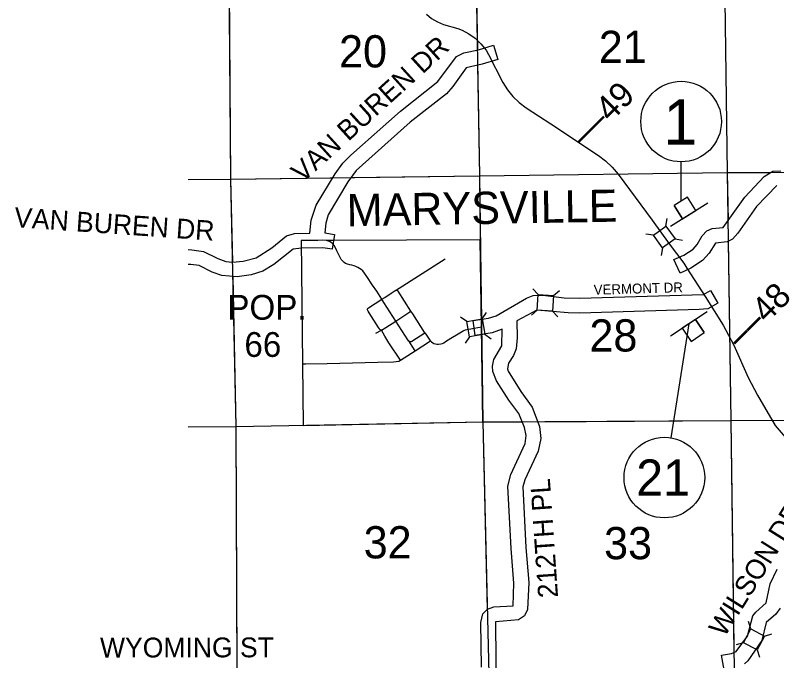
# Model space of a CAD drawing. Extents: x 10133 to 81668, y 5524 to 11018.
# Drawn here: x 22990.7 to 23374.6, y 8304.5 to 8630.1 of the extents above; entities that cross this region are included whole.
import ezdxf

# ---------------------------------------------------------------- set-up
doc = ezdxf.new("R2010")
doc.units = 0
for name, color, linetype in [('Default', 7, 'Continuous'), ('DisBoundDim', 7, 'Continuous'), ('DisCLMLOR', 7, 'Continuous'), ('DisCLMLSUR', 7, 'Continuous'), ('trf_SignNumber_Text', 7, 'Continuous')]:
    doc.layers.add(name, color=color, linetype=linetype)

msp = doc.modelspace()

# ---------------------------------------------------------------- linework, layer by layer
at = {"layer": 'Default'}
for p, q in [((23318.72, 8523.69), (23319.35, 8527.55)), ((23312.36, 8519.13), (23308.5, 8519.76)), ((23323.28, 8517.33), (23327.14, 8516.7)), ((23316.93, 8512.77), (23316.29, 8508.91)), ((23254.27, 8489.24), (23251.67, 8492.17)), ((23262.08, 8488.76), (23265.01, 8491.35)), ((23253.79, 8481.43), (23250.86, 8478.83)), ((23261.6, 8480.95), (23264.19, 8478.02)), ((23218.34, 8475.62), (23215.15, 8477.88)), ((23226.05, 8476.96), (23228.31, 8480.16)), ((23227.39, 8469.25), (23230.59, 8467)), ((23219.68, 8467.91), (23217.43, 8464.72)), ((23361.49, 8320.59), (23360.33, 8324.32)), ((23368.42, 8316.94), (23372.16, 8318.1)), ((23357.85, 8313.66), (23354.11, 8312.5)), ((23364.77, 8310.02), (23365.93, 8306.28))]:
    msp.add_line(p, q, dxfattribs=at)
for points in [[(23098.21, 8672.61), (23099.25, 8547.47)], [(23222.61, 8674.33), (23223.65, 8612.58)], [(23222.61, 8674.33), (23224.71, 8549.21)], [(23347.95, 8674.98), (23349.65, 8550.78)], [(23347.95, 8674.98), (23349.65, 8550.78)], [(23098.45, 8643.94), (23099.25, 8547.47)], [(23197.97, 8630.68), (23200.59, 8628.51), (23203.51, 8626.75), (23206.66, 8625.44), (23213.77, 8623.53), (23216.07, 8622.59), (23219.42, 8620.81), (23222.51, 8618.6), (23225.42, 8615.72), (23228.03, 8612.56), (23229.23, 8610.29), (23236.44, 8596.25), (23238.76, 8592.52), (23241.52, 8589.1), (23244.68, 8586.04), (23248.18, 8583.38), (23260.61, 8575.38), (23284.71, 8559.38), (23288.31, 8556.64), (23291.57, 8553.51), (23294.55, 8549.94), (23311.75, 8526.77), (23320.26, 8514.81), (23327.73, 8505.03), (23329.17, 8502.59), (23338.51, 8488.26), (23347.55, 8473.86), (23352.91, 8463.81), (23360.18, 8447.48), (23364.81, 8438.57), (23373.81, 8423.25), (23378.83, 8417.33)], [(23077.9, 8511.95), (23079.75, 8511.85), (23085.66, 8511.02), (23092.78, 8507.43), (23096.91, 8506.01), (23100.2, 8505.63), (23105.64, 8506.07), (23112.18, 8507.86), (23120.04, 8512.89), (23127.43, 8518.93), (23131.39, 8519.98), (23139.24, 8520.21), (23139.94, 8526.73), (23142.36, 8534.42), (23151.95, 8550.14), (23155.87, 8555.57), (23159.79, 8559.64), (23184.9, 8581.79), (23203.78, 8596.72), (23213.05, 8609.35), (23216.89, 8611.22), (23224.27, 8612.7), (23231.72, 8614.96), (23233.9, 8607.79), (23226.06, 8605.41), (23217.92, 8603.63), (23211.3, 8594.23), (23208.15, 8590.54), (23189.82, 8576.13), (23162.56, 8551.84), (23158.31, 8546.17), (23148.39, 8529.53), (23147.3, 8525.26), (23146.74, 8520.34), (23151.69, 8519.62), (23150.46, 8512.22), (23145.71, 8512.89), (23134.96, 8512.71), (23130.84, 8512.19), (23121, 8504.33), (23115.47, 8501.12), (23109.58, 8499.23), (23102.61, 8498.14), (23094.82, 8498.8), (23089.95, 8500.47), (23083.44, 8503.85), (23079.24, 8504.36), (23077.9, 8504.44)], [(23223.77, 8604.98), (23224.71, 8549.21)], [(23224.71, 8549.21), (23349.65, 8550.78)], [(23224.71, 8549.21), (23349.65, 8550.78)], [(23374.64, 8544.26), (23364.3, 8533.7), (23354.87, 8520.22), (23352.26, 8517.21), (23349.55, 8515.83), (23343.65, 8515.16), (23340.55, 8510.18), (23337.2, 8506.42), (23331.23, 8502.49), (23325.82, 8500.08), (23322.77, 8506.93), (23327.77, 8509.15), (23332.4, 8512.19), (23334.44, 8514.53), (23336.97, 8518.93), (23339.37, 8521.34), (23342.05, 8522.62), (23347.58, 8523.15), (23358.42, 8538.36), (23368.25, 8548.82), (23372.53, 8551.5), (23376.68, 8551.69)], [(23349.65, 8550.78), (23475.87, 8551.39)], [(23349.65, 8550.78), (23371.25, 8550.88)], [(23349.65, 8550.78), (23350.01, 8526.43)], [(23349.65, 8550.78), (23351.48, 8425.65)], [(23077.9, 8547.35), (23099.25, 8547.47)], [(23077.9, 8547.35), (23099.25, 8547.47)], [(23099.25, 8547.47), (23224.71, 8549.21)], [(23099.25, 8547.47), (23150.73, 8548.18)], [(23099.25, 8547.47), (23100.14, 8505.64)], [(23099.25, 8547.47), (23101.92, 8422.63)], [(23159.81, 8548.31), (23224.71, 8549.21)], [(23224.71, 8549.21), (23225.14, 8516.8)], [(23224.71, 8549.21), (23226.36, 8424.99)], [(23164.27, 8502.47), (23163.37, 8502.93), (23162.33, 8503.45), (23161.52, 8503.76), (23160.45, 8504.01), (23159.34, 8504.22), (23158.1, 8504.59), (23157.18, 8504.99), (23156.5, 8505.46), (23155.94, 8505.92), (23155.48, 8506.35), (23155.05, 8506.87), (23154.59, 8507.61), (23154.03, 8509.03), (23152.8, 8511.28), (23152.09, 8512.76), (23151.41, 8513.96), (23150.8, 8514.83), (23150, 8515.54), (23149.16, 8516.06), (23148.18, 8516.4), (23147.37, 8516.53)], [(23350.16, 8516.02), (23351.48, 8425.65)], [(23182.37, 8491.33), (23207.36, 8507.27)], [(23225.25, 8508.82), (23225.68, 8476.7)], [(23189.04, 8465.84), (23188.93, 8465.91), (23188.59, 8466.34), (23182.56, 8475.86), (23176.57, 8485.33), (23175.55, 8486.89), (23172.96, 8490.88), (23170.8, 8494.05), (23167.91, 8498.43), (23166.76, 8500.12), (23165.9, 8501.14), (23165.1, 8501.82), (23164.27, 8502.47)], [(23100.3, 8498.22), (23101.92, 8422.63)], [(23175.25, 8471.3), (23174.81, 8471.39), (23174.5, 8471.61), (23174.29, 8471.89), (23173.73, 8472.66), (23169.08, 8479.99), (23168.55, 8480.95), (23168.34, 8481.57), (23168.31, 8481.97), (23168.49, 8482.28), (23168.83, 8482.52), (23175.55, 8486.89), (23176.94, 8487.79), (23180.14, 8489.89), (23182.24, 8491.25), (23182.37, 8491.33)], [(23190.19, 8480.85), (23183.7, 8490.89), (23183.48, 8491.2), (23183.27, 8491.32), (23182.9, 8491.38), (23182.37, 8491.33)], [(23225.65, 8301.39), (23225.33, 8323.82), (23226.46, 8328.26), (23228.81, 8330.64), (23231.88, 8331.83), (23241.64, 8332.19), (23242.06, 8343.74), (23240.65, 8361.2), (23239.08, 8392.67), (23240.56, 8398.55), (23247.68, 8414.17), (23248.17, 8418.22), (23247.35, 8422.27), (23244.57, 8429.19), (23239.53, 8436), (23233.33, 8445.73), (23231.44, 8450.4), (23231.27, 8453.11), (23231.92, 8456.46), (23235.92, 8463.41), (23236.19, 8471.73), (23231.03, 8470.01), (23222.52, 8468.66), (23221.49, 8476.09), (23229.28, 8477.3), (23233.16, 8478.6), (23248.45, 8487.37), (23251.85, 8488.77), (23256.65, 8488.93), (23267.41, 8487.68), (23275.27, 8487.42), (23337.63, 8489.29), (23341.13, 8491.33), (23344.91, 8484.85), (23339.78, 8481.99), (23335.54, 8481.69), (23275.28, 8479.93), (23269.5, 8480), (23253.59, 8481.45), (23243.62, 8475.92), (23243.76, 8467.35), (23243.25, 8461.82), (23241.88, 8458.45), (23239.27, 8454.69), (23238.81, 8451.79), (23239.13, 8450.63), (23245.63, 8440.36), (23251.31, 8432.49), (23255, 8422.77), (23255.64, 8416.59), (23254.24, 8410.27), (23247.57, 8395.86), (23246.58, 8392.19), (23248.14, 8361.67), (23249.56, 8343.98), (23248.97, 8330.4), (23247.49, 8327.24), (23244.32, 8325.11), (23232.86, 8324.23), (23233.2, 8285.33)], [(23175.25, 8471.3), (23177.58, 8472.6), (23182.56, 8475.86), (23190.19, 8480.85)], [(23197.14, 8469.98), (23191.07, 8479.48), (23190.19, 8480.85)], [(23189.04, 8465.84), (23189.14, 8465.78), (23189.51, 8465.66), (23189.95, 8465.63), (23190.38, 8465.66), (23190.69, 8465.81), (23197.14, 8469.98), (23197.94, 8468.72), (23199.73, 8466.26), (23200.06, 8465.89), (23200.53, 8465.36), (23201.15, 8464.96), (23201.76, 8464.62), (23202.5, 8464.41), (23203.24, 8464.25), (23204.14, 8464.22), (23205.22, 8464.35), (23206.08, 8464.65), (23206.7, 8464.93), (23207.62, 8465.58), (23210.24, 8467.18), (23213.94, 8469.49), (23216.44, 8470.88), (23217.73, 8471.41), (23219, 8471.78), (23220.29, 8471.99), (23222.08, 8472.3), (23225.72, 8472.89)], [(23172.44, 8469.73), (23175.25, 8471.3)], [(23184.82, 8456.11), (23178.99, 8464.97), (23176.98, 8468.24), (23175.25, 8471.3)], [(23225.78, 8469.12), (23226.36, 8424.99)], [(23192.31, 8460.92), (23190.85, 8463.22), (23189.99, 8464.57), (23189.04, 8465.84)], [(23192.31, 8460.92), (23200.06, 8465.89)], [(23184.82, 8456.11), (23192.31, 8460.92)], [(23135.52, 8454.23), (23137.11, 8454.25), (23147.99, 8454.5), (23173.52, 8455.09), (23181.31, 8455.39), (23184.09, 8455.64), (23184.82, 8456.11)], [(23077.9, 8422.46), (23101.92, 8422.63)], [(23077.9, 8422.46), (23101.92, 8422.63)], [(23101.92, 8422.63), (23226.36, 8424.99)], [(23101.92, 8422.63), (23226.36, 8424.99)], [(23101.92, 8422.63), (23102.42, 8301.26)], [(23101.92, 8422.63), (23102.43, 8297.56)], [(23226.36, 8424.99), (23351.48, 8425.65)], [(23226.36, 8424.99), (23246.33, 8425.09)], [(23226.36, 8424.99), (23228.6, 8330.48)], [(23226.36, 8424.99), (23229.38, 8297.77)], [(23254.25, 8425.14), (23351.48, 8425.65)], [(23351.48, 8425.65), (23476.08, 8426.3)], [(23351.48, 8425.65), (23476.08, 8426.3)], [(23351.48, 8425.65), (23352.98, 8308.77)], [(23351.48, 8425.65), (23353.1, 8299.45)], [(23348.02, 8300.01), (23346.77, 8307.41), (23351.76, 8308.25), (23354.09, 8309.24), (23359.79, 8317.01), (23362.51, 8327.14), (23363.95, 8329.12), (23369.18, 8333.82), (23371.22, 8343.4), (23374.7, 8350.8)], [(23376.21, 8331.1), (23374.1, 8327.97), (23369.28, 8323.84), (23367.07, 8314.75), (23360.05, 8304.58), (23358.32, 8303.03)]]:
    msp.add_lwpolyline(points, dxfattribs=at)
for points in [[(23316.93, 8512.77), (23312.36, 8519.13), (23318.72, 8523.69), (23323.28, 8517.33)], [(23225.14, 8516.8), (23150.78, 8516.47), (23147.38, 8516.59), (23145.77, 8516.65), (23143.19, 8516.57), (23139.7, 8516.46), (23134.86, 8516.46), (23135.52, 8454.23), (23135.85, 8423.27), (23226.36, 8424.99), (23225.72, 8472.93)], [(23254.27, 8489.24), (23262.08, 8488.76), (23261.6, 8480.95), (23253.79, 8481.43)], [(23227.39, 8469.25), (23219.68, 8467.91), (23218.34, 8475.62), (23226.05, 8476.96)], [(23368.42, 8316.94), (23364.77, 8310.02), (23357.85, 8313.66), (23361.49, 8320.59)]]:
    msp.add_lwpolyline(points, close=True, dxfattribs=at)
at = {"layer": 'DisBoundDim'}
for p, q in [((23329.59, 8538.39), (23322.8, 8534.15)), ((23333.82, 8531.6), (23329.59, 8538.39)), ((23339.82, 8535.34), (23321.04, 8523.63)), ((23327.03, 8527.37), (23322.8, 8534.15)), ((23321.08, 8468.36), (23339.49, 8480.65)), ((23333.61, 8476.72), (23338.05, 8470.07)), ((23326.96, 8472.28), (23331.4, 8465.63)), ((23331.4, 8465.63), (23338.05, 8470.07))]:
    msp.add_line(p, q, dxfattribs=at)
at = {"layer": 'DisCLMLOR'}
for p, q in [((23329.59, 8538.39), (23322.8, 8534.15)), ((23329.59, 8538.39), (23322.8, 8534.15)), ((23329.59, 8538.39), (23322.8, 8534.15)), ((23329.59, 8538.39), (23322.8, 8534.15)), ((23333.82, 8531.6), (23329.59, 8538.39)), ((23333.82, 8531.6), (23329.59, 8538.39)), ((23333.82, 8531.6), (23329.59, 8538.39)), ((23333.82, 8531.6), (23329.59, 8538.39)), ((23322.8, 8534.15), (23327.03, 8527.37)), ((23322.8, 8534.15), (23327.03, 8527.37)), ((23322.8, 8534.15), (23327.03, 8527.37)), ((23322.8, 8534.15), (23327.03, 8527.37)), ((23327.03, 8527.37), (23333.82, 8531.6)), ((23327.03, 8527.37), (23333.82, 8531.6)), ((23327.03, 8527.37), (23333.82, 8531.6)), ((23327.03, 8527.37), (23333.82, 8531.6)), ((23333.61, 8476.72), (23326.96, 8472.28)), ((23333.61, 8476.72), (23326.96, 8472.28)), ((23333.61, 8476.72), (23326.96, 8472.28)), ((23333.61, 8476.72), (23326.96, 8472.28)), ((23338.05, 8470.07), (23333.61, 8476.72)), ((23338.05, 8470.07), (23333.61, 8476.72)), ((23338.05, 8470.07), (23333.61, 8476.72)), ((23338.05, 8470.07), (23333.61, 8476.72)), ((23326.96, 8472.28), (23331.4, 8465.63)), ((23326.96, 8472.28), (23331.4, 8465.63)), ((23326.96, 8472.28), (23331.4, 8465.63)), ((23326.96, 8472.28), (23331.4, 8465.63)), ((23331.4, 8465.63), (23338.05, 8470.07)), ((23331.4, 8465.63), (23338.05, 8470.07)), ((23331.4, 8465.63), (23338.05, 8470.07)), ((23331.4, 8465.63), (23338.05, 8470.07))]:
    msp.add_line(p, q, dxfattribs=at)
at = {"layer": 'DisCLMLSUR'}
for p, q in [((23326.29, 8556.19), (23326.2, 8536.27)), ((23330.28, 8474.5), (23321.14, 8417.03))]:
    msp.add_line(p, q, dxfattribs=at)
at = {"layer": 'trf_SignNumber_Text'}
for centre in [(23326.38, 8576.52), (23317.95, 8396.95)]:
    msp.add_circle(centre, 20.33, dxfattribs=at)

# ---------------------------------------------------------------- texts
at = {"layer": 'Default'}
for s, height, rotation, p in [('21', 16.25, 0.0233, (23284.87, 8606.06)), ('VAN BUREN DR', 10, 42.2182, (23135.46, 8545.26)), ('20', 16.25, 0.0225, (23153.93, 8603.81)), ('‒‒49', 12.5, 45, (23277.55, 8562.64)), ('MARYSVILLE', 16.25, 1, (23157.91, 8523.65)), ('VAN BUREN DR', 10, 356.1025, (22989.95, 8523.28)), ('VERMONT DR', 5, 1.6573, (23282.37, 8489.15)), ('‒‒48', 12.5, 45, (23356.35, 8461.29)), ('28', 16.25, 0.0232, (23280.15, 8460.52)), ('212TH PL', 10, 93.9665, (23264.35, 8336.57)), ('WILSON DR', 10, 57.982, (23348.19, 8315.99)), ('32', 16.25, 0.0226, (23166.34, 8356.17)), ('33', 16.25, 0.0233, (23287.52, 8355.76)), ('WYOMING ST', 10, 0.0915, (23033.43, 8306.17))]:
    msp.add_text(s, height=height, rotation=rotation, dxfattribs=at).set_placement(p)
for s, p in [('POP.', (23097.61, 8476.56)), ('66', (23106.21, 8457.81))]:
    msp.add_text(s, height=12.5, dxfattribs=at).set_placement(p)
at = {"layer": 'trf_SignNumber_Text'}
for s, height, p in [('1', 22.82, (23317.48, 8564.91)), ('21', 18.258, (23303.72, 8387.82))]:
    msp.add_text(s, height=height, dxfattribs=at).set_placement(p)

doc.saveas('drawing.dxf')
